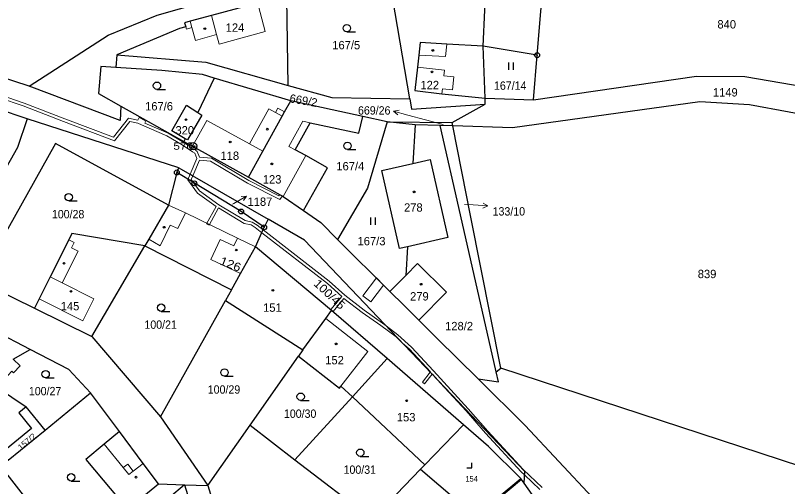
# Model space of a CAD drawing. Extents: x -758887 to -754328, y -1031688 to -1029144.
# Drawn here: x -756179.9 to -756022.6, y -1030514 to -1030418.1 of the extents above; entities that cross this region are included whole.
import ezdxf
from ezdxf.enums import TextEntityAlignment as Align

# ---------------------------------------------------------------- set-up
doc = ezdxf.new("R2010")
doc.units = 0
doc.header["$LTSCALE"] = 0.68
for name, color, linetype, lineweight in [('1', 7, 'Continuous', 25), ('13', 7, 'Continuous', 13), ('3', 7, 'Continuous', 25), ('4', 7, 'Continuous', 13), ('5', 7, 'Continuous', 25), ('7', 7, 'Continuous', 13), ('8', 7, 'Continuous', 25)]:
    doc.layers.add(name, color=color, linetype=linetype, lineweight=lineweight)
doc.layers.add('2', color=7, linetype='Continuous')

msp = doc.modelspace()

# ---------------------------------------------------------------- linework, layer by layer
at = {"layer": '1'}
for p, q in [((-756073.62, -1030426.17), (-756084.58, -1030424.35)), ((-756159.24, -1030426.06), (-756159.41, -1030428.66)), ((-756177.1, -1030432.5), (-756186.27, -1030429.51)), ((-756139.4, -1030430.81), (-756142.74, -1030437.81)), ((-756123.8, -1030435.45), (-756139.4, -1030430.81)), ((-756084.18, -1030436.12), (-756084.22, -1030434.94)), ((-756177.49, -1030439.12), (-756185.37, -1030436.47)), ((-756109.09, -1030438.68), (-756123.8, -1030435.45)), ((-756090.93, -1030439.9), (-756084.18, -1030436.12)), ((-756146.57, -1030449.09), (-756177.49, -1030439.12)), ((-756104.15, -1030439.76), (-756109.09, -1030438.68)), ((-756104.15, -1030439.76), (-756090.93, -1030439.9)), ((-756098.46, -1030440.33), (-756104.15, -1030439.76)), ((-756090.8, -1030440.57), (-756090.93, -1030439.9)), ((-756098.46, -1030440.33), (-756098.95, -1030448.2)), ((-756093.4, -1030440.49), (-756098.46, -1030440.33)), ((-756090.8, -1030440.57), (-756093.4, -1030440.49)), ((-756145.3, -1030443.16), (-756145.56, -1030443.71)), ((-756147.01, -1030450.03), (-756146.57, -1030449.09)), ((-756146.57, -1030449.09), (-756128.38, -1030459.56)), ((-756128.38, -1030459.56), (-756129.21, -1030461.2)), ((-756131, -1030465.16), (-756129.21, -1030461.2)), ((-756114.26, -1030463.66), (-756103.59, -1030474.26)), ((-756091.81, -1030463.3), (-756100.01, -1030465.15)), ((-756115.47, -1030478.16), (-756131, -1030465.16)), ((-756103.59, -1030474.26), (-756100.37, -1030470.99)), ((-756135.9, -1030473.95), (-756137.1, -1030476.09)), ((-756092.08, -1030474.4), (-756097.71, -1030480.11)), ((-756137.1, -1030476.09), (-756121.35, -1030486.18)), ((-756180.37, -1030488.07), (-756176.86, -1030486.08)), ((-756081.94, -1030490.6), (-756081.04, -1030489.91)), ((-756113.89, -1030493.93), (-756113.58, -1030493.55)), ((-756113.58, -1030493.55), (-756111.25, -1030495.74)), ((-756183.66, -1030493.75), (-756177.71, -1030497.78)), ((-756173.85, -1030502.5), (-756164.57, -1030494.9)), ((-756158.71, -1030502.76), (-756164.57, -1030494.9)), ((-756122.94, -1030508.54), (-756111.25, -1030495.74)), ((-756150.36, -1030499.82), (-756140.69, -1030513.8)), ((-756132.1, -1030501.51), (-756122.94, -1030508.54)), ((-756076.82, -1030512.55), (-756076.96, -1030512.35)), ((-756145.46, -1030513.63), (-756148.51, -1030516.24)), ((-756140.69, -1030513.8), (-756139.63, -1030517.33)), ((-756076.28, -1030513.28), (-756076.82, -1030512.55)), ((-756074.6, -1030515.58), (-756076.28, -1030513.28))]:
    msp.add_line(p, q, dxfattribs=at)
for points in [[(-756177.1, -1030432.5), (-756161.02, -1030422.06), (-756151.02, -1030418.01), (-756091.41, -1030401.05), (-756048.53, -1030383.75), (-756038.26, -1030382.8), (-756029.12, -1030383.41)], [(-756084.22, -1030434.94), (-756074.39, -1030435.22), (-756073.62, -1030426.17), (-756072.87, -1030417.3), (-756071.16, -1030397.2), (-756083.61, -1030402.28)], [(-756084.58, -1030424.35), (-756083.61, -1030402.28), (-756104.05, -1030408.71)], [(-756099.56, -1030435.05), (-756104.05, -1030408.71), (-756124.62, -1030414.55)], [(-756159.24, -1030426.06), (-756141.08, -1030427.61), (-756124.32, -1030432.31), (-756124.62, -1030414.55)], [(-756124.62, -1030414.55), (-756130.39, -1030416.19), (-756130.55, -1030415.6), (-756139.97, -1030418.11), (-756144.28, -1030419.26), (-756145.41, -1030419.56), (-756145.19, -1030420.4), (-756146.46, -1030420.76), (-756159.24, -1030426.06)], [(-756002.56, -1030425.47), (-756003.83, -1030436.47), (-756008.02, -1030441.53), (-756014.19, -1030439.23), (-756030.36, -1030436.26), (-756040.48, -1030435.67), (-756078.66, -1030440.94), (-756090.8, -1030440.57)], [(-756074.39, -1030435.22), (-756041.14, -1030430.43), (-756031.32, -1030430.49), (-756011.88, -1030433.81), (-756002.56, -1030425.47)], [(-756159.41, -1030428.66), (-756162.47, -1030428.46), (-756162.99, -1030433.99), (-756158.39, -1030436.56), (-756145.56, -1030443.71)], [(-756139.4, -1030430.81), (-756141.8, -1030430.09), (-756150.09, -1030429.28), (-756159.41, -1030428.66)], [(-756158.39, -1030436.56), (-756158.54, -1030439.45), (-756177.1, -1030432.5)], [(-756124.32, -1030432.31), (-756115.46, -1030434.8), (-756099.56, -1030435.05)], [(-756099.56, -1030435.05), (-756099.2, -1030437.14), (-756084.18, -1030436.12)], [(-756145.3, -1030443.16), (-756148.05, -1030441.57), (-756145.03, -1030436.36), (-756142.74, -1030437.81)], [(-756132.39, -1030450.99), (-756129.46, -1030445.69), (-756125.55, -1030438.6), (-756125.06, -1030437.73), (-756123.8, -1030435.45)], [(-756142.74, -1030437.81), (-756141.88, -1030438.35), (-756144.84, -1030443.42), (-756145.3, -1030443.16)], [(-756177.49, -1030439.12), (-756179.45, -1030444.96), (-756182.43, -1030450.22), (-756185.07, -1030453.38), (-756190.89, -1030458.98), (-756194.45, -1030461.45)], [(-756121.19, -1030457.81), (-756116.32, -1030449.08), (-756120.75, -1030446.6), (-756122.91, -1030445.4), (-756119.84, -1030439.91), (-756109.91, -1030442.01), (-756109.09, -1030438.68)], [(-756104.15, -1030439.76), (-756108.19, -1030453.27), (-756114.26, -1030463.66)], [(-756081.94, -1030490.6), (-756089.25, -1030458.65), (-756093.4, -1030440.49)], [(-756081.04, -1030489.91), (-756087.13, -1030459.12), (-756090.8, -1030440.57)], [(-756148.68, -1030456.69), (-756171.73, -1030444.13), (-756185.68, -1030469.03), (-756184.6, -1030473.45), (-756176.03, -1030477.68)], [(-756145.56, -1030443.71), (-756143.81, -1030444.68), (-756132.39, -1030450.99)], [(-756100.01, -1030465.15), (-756101.66, -1030465.52), (-756105.25, -1030449.62), (-756098.95, -1030448.2), (-756095.4, -1030447.4), (-756091.81, -1030463.3)], [(-756129.21, -1030461.2), (-756133.92, -1030457.98), (-756143.43, -1030452.25), (-756147.01, -1030450.03), (-756148.68, -1030456.69)], [(-756132.39, -1030450.99), (-756125.36, -1030454.91), (-756121.19, -1030457.81)], [(-756148.68, -1030456.69), (-756152.73, -1030463.63), (-756153.5, -1030464.95), (-756135.9, -1030473.95)], [(-756121.19, -1030457.81), (-756117.7, -1030460.24), (-756114.26, -1030463.66)], [(-756076.28, -1030513.28), (-756076.15, -1030510.91), (-756120.98, -1030463.81), (-756128.38, -1030459.56)], [(-756153.5, -1030464.95), (-756168.36, -1030462.45), (-756169.01, -1030463.74), (-756172.81, -1030471.29), (-756175.06, -1030475.76), (-756176.03, -1030477.68)], [(-756176.03, -1030477.68), (-756164.32, -1030483.47), (-756153.5, -1030464.95)], [(-756135.9, -1030473.95), (-756134.05, -1030470.63), (-756131, -1030465.16)], [(-756100.01, -1030465.15), (-756100.37, -1030470.99), (-756097.98, -1030468.57), (-756092.08, -1030474.4)], [(-756097.71, -1030480.11), (-756100.75, -1030477.09), (-756103.59, -1030474.26)], [(-756164.32, -1030483.47), (-756150.36, -1030499.82), (-756137.1, -1030476.09)], [(-756176.86, -1030486.08), (-756191.51, -1030478.5), (-756196.35, -1030487.29)], [(-756121.35, -1030486.18), (-756116.65, -1030479.75), (-756115.47, -1030478.16)], [(-756111.25, -1030495.74), (-756104.15, -1030487.95), (-756115.47, -1030478.16)], [(-756097.71, -1030480.11), (-756093.96, -1030483.83), (-756085.66, -1030492.03)], [(-756164.57, -1030494.9), (-756169.02, -1030490.14), (-756176.86, -1030486.08)], [(-756121.35, -1030486.18), (-756122.25, -1030487.42), (-756113.89, -1030493.93)], [(-756183.66, -1030493.75), (-756180.63, -1030490.5), (-756180.26, -1030490.84), (-756178.95, -1030489.42), (-756180.37, -1030488.07)], [(-756140.69, -1030513.8), (-756132.1, -1030501.51), (-756122.25, -1030487.42)], [(-756111.25, -1030495.74), (-756096.52, -1030509.6), (-756088.61, -1030501.4), (-756104.15, -1030487.95)], [(-756000.74, -1030512.89), (-756019.93, -1030509.92), (-756081.04, -1030489.91)], [(-756085.66, -1030492.03), (-756081.46, -1030492.68), (-756081.94, -1030490.6)], [(-756056.08, -1030523.3), (-756062.34, -1030516.25), (-756076.02, -1030501.54), (-756085.66, -1030492.03)], [(-756177.71, -1030497.78), (-756179.18, -1030498.98), (-756176.58, -1030502.15), (-756182.62, -1030507.1), (-756181.35, -1030508.64)], [(-756181.35, -1030508.64), (-756173.85, -1030502.5), (-756177.71, -1030497.78)], [(-756076.96, -1030512.35), (-756083.49, -1030505.82), (-756088.61, -1030501.4)], [(-756158.71, -1030502.76), (-756161.82, -1030505.36), (-756165.54, -1030508.47), (-756157.04, -1030518.62), (-756150.75, -1030513.43)], [(-756150.75, -1030513.43), (-756153.83, -1030509.3), (-756158.71, -1030502.76)], [(-756181.35, -1030508.64), (-756182.88, -1030509.9), (-756168.68, -1030528.11)], [(-756122.94, -1030508.54), (-756107.17, -1030520.63), (-756097.36, -1030510.47)], [(-756096.52, -1030509.6), (-756097.36, -1030510.47), (-756086.2, -1030520.01), (-756076.96, -1030512.35)], [(-756150.75, -1030513.43), (-756145.46, -1030513.63), (-756140.69, -1030513.8)], [(-756145.46, -1030513.63), (-756140.48, -1030529.53), (-756141.51, -1030530.23)], [(-756076.82, -1030512.55), (-756081.44, -1030516.41), (-756079.31, -1030519.4), (-756074.6, -1030515.58)]]:
    msp.add_lwpolyline(points, dxfattribs=at)
msp.add_lwpolyline([(-756084.58, -1030424.35), (-756092, -1030423.92), (-756097.44, -1030423.61), (-756097.69, -1030426.13), (-756097.97, -1030428.61), (-756098.51, -1030433.38), (-756093.03, -1030434), (-756084.22, -1030434.94)], close=True, dxfattribs=at)
at = {"layer": '13'}
for points in [[(-756183.19, -1030434.83), (-756178.28, -1030436.47), (-756170.07, -1030439.67), (-756159.7, -1030443.6)], [(-756159.7, -1030443.6), (-756156.59, -1030439.67), (-756154.96, -1030440.01), (-756154.2, -1030440.34), (-756149.07, -1030442.61), (-756145.9, -1030444.43), (-756143.81, -1030445.84), (-756143.37, -1030446.14), (-756142.91, -1030447.21), (-756144.29, -1030450.4), (-756143.77, -1030450.7), (-756142.39, -1030447.53), (-756140.15, -1030447.73), (-756132.62, -1030452.21), (-756126.04, -1030455.55), (-756125.5, -1030454.83), (-756126.03, -1030454.53), (-756126.22, -1030454.79), (-756132.34, -1030451.69), (-756139.97, -1030447.15), (-756142.38, -1030446.93), (-756142.89, -1030445.74), (-756143.23, -1030445.51), (-756143, -1030445.13), (-756143.52, -1030444.84), (-756143.73, -1030445.17), (-756145.58, -1030443.93), (-756148.79, -1030442.07), (-756153.52, -1030439.98), (-756153.36, -1030439.73), (-756153.51, -1030439.45), (-756154.69, -1030438.87), (-756154.95, -1030439.4), (-756156.83, -1030439.01), (-756159.9, -1030442.88), (-756169.85, -1030439.11), (-756178.08, -1030435.91), (-756183.01, -1030434.25)], [(-756072.61, -1030514.16), (-756076.46, -1030510.55), (-756083.66, -1030502.71), (-756087.64, -1030498.17), (-756094.74, -1030490.44), (-756099.21, -1030485.63), (-756101.97, -1030483.08), (-756104.35, -1030481.29), (-756105.11, -1030480.71), (-756108.87, -1030478.1), (-756112.81, -1030475.03), (-756115.96, -1030472.18), (-756129.45, -1030461.74), (-756129.71, -1030462.3), (-756116.34, -1030472.64), (-756113.42, -1030475.28), (-756115.65, -1030477.97), (-756115.18, -1030478.34), (-756112.97, -1030475.67), (-756109.23, -1030478.58), (-756105.47, -1030481.19), (-756102.35, -1030483.54), (-756101.1, -1030484.7), (-756099.63, -1030486.05), (-756095.36, -1030490.66), (-756095.39, -1030490.7), (-756096.99, -1030492.72), (-756096.53, -1030493.11), (-756094.97, -1030491.14), (-756094.94, -1030491.1), (-756093.28, -1030492.91), (-756088.08, -1030498.57), (-756084.1, -1030503.11), (-756076.88, -1030510.97), (-756076.19, -1030511.62), (-756073.05, -1030514.58)]]:
    msp.add_lwpolyline(points, dxfattribs=at)
for points in [[(-756142.84, -1030444.88), (-756143.37, -1030444.6), (-756143.52, -1030444.84), (-756143, -1030445.13)], [(-756133.28, -1030460.4), (-756131.88, -1030460.69), (-756131.03, -1030461.28), (-756129.71, -1030462.3), (-756129.45, -1030461.74), (-756130.67, -1030460.8), (-756131.64, -1030460.13), (-756133.06, -1030459.84), (-756138.46, -1030456.61), (-756142.39, -1030453.81), (-756144.09, -1030451.44), (-756143.77, -1030450.7), (-756144.29, -1030450.4), (-756144.77, -1030451.52), (-756142.81, -1030454.25), (-756139.02, -1030456.94), (-756140.95, -1030460.53), (-756140.41, -1030460.79), (-756138.51, -1030457.27)], [(-756104.9, -1030472.96), (-756106.36, -1030471.52), (-756109.1, -1030475.19), (-756107.48, -1030476.41)]]:
    msp.add_lwpolyline(points, close=True, dxfattribs=at)
at = {"layer": '3'}
for p, q in [((-756112.393, -1030421.41), (-756110.643, -1030421.41)), ((-756079.401, -1030429.13), (-756079.401, -1030427.63)), ((-756078.4, -1030429.13), (-756078.4, -1030427.63)), ((-756151.053, -1030433.13), (-756149.303, -1030433.13)), ((-756112.263, -1030445.36), (-756110.513, -1030445.36)), ((-756169.033, -1030455.83), (-756167.283, -1030455.83)), ((-756107.511, -1030460.68), (-756107.511, -1030459.18)), ((-756106.51, -1030460.68), (-756106.51, -1030459.18)), ((-756150.193, -1030478.32), (-756148.443, -1030478.32)), ((-756173.733, -1030491.86), (-756171.983, -1030491.86)), ((-756137.293, -1030491.53), (-756135.543, -1030491.53)), ((-756121.783, -1030496.45), (-756120.033, -1030496.45)), ((-756109.633, -1030507.85), (-756107.883, -1030507.85)), ((-756168.533, -1030512.86), (-756166.783, -1030512.86))]:
    msp.add_line(p, q, dxfattribs=at)
msp.add_lwpolyline([(-756087.941, -1030510.18), (-756086.94, -1030510.18), (-756086.94, -1030509.18)], dxfattribs=at)
for centre in [(-756112.3929, -1030420.6598), (-756151.0529, -1030432.3798), (-756112.2629, -1030444.6098), (-756169.0329, -1030455.0798), (-756150.1929, -1030477.5698), (-756173.7329, -1030491.1098), (-756137.2929, -1030490.7798), (-756121.7829, -1030495.6998), (-756109.6329, -1030507.0998), (-756168.5329, -1030512.1098)]:
    msp.add_circle(centre, 0.75, dxfattribs=at)
at = {"layer": '4'}
for p, q in [((-756130.39, -1030416.19), (-756129.02, -1030421.33)), ((-756138.93, -1030421.98), (-756139.97, -1030418.11)), ((-756143.96, -1030420.53), (-756144.28, -1030419.26)), ((-756145.19, -1030420.4), (-756145.07, -1030420.84)), ((-756145.07, -1030420.84), (-756143.96, -1030420.53)), ((-756143.96, -1030420.53), (-756143.22, -1030423.18)), ((-756138.93, -1030421.98), (-756143.22, -1030423.18)), ((-756138.93, -1030421.98), (-756138.36, -1030423.91)), ((-756138.36, -1030423.91), (-756129.02, -1030421.33)), ((-756092, -1030423.92), (-756092.25, -1030426.44)), ((-756097.69, -1030426.13), (-756092.25, -1030426.44)), ((-756092.49, -1030429.22), (-756097.97, -1030428.61)), ((-756132.2, -1030444.24), (-756128.26, -1030437.1)), ((-756126.9, -1030437.85), (-756125.55, -1030438.6)), ((-756140.91, -1030439.43), (-756143.81, -1030444.68)), ((-756120.75, -1030446.6), (-756125.36, -1030454.91)), ((-756146.8, -1030461.48), (-756145.25, -1030458.28)), ((-756150.38, -1030464.97), (-756148.33, -1030460.74)), ((-756148.33, -1030460.74), (-756146.8, -1030461.48)), ((-756169.01, -1030463.74), (-756167.9, -1030464.31)), ((-756152.73, -1030463.63), (-756150.38, -1030464.97)), ((-756140.1, -1030467.73), (-756138.16, -1030463.67)), ((-756131, -1030465.16), (-756134.65, -1030463.41)), ((-756167.9, -1030464.31), (-756168.44, -1030465.38)), ((-756167.1, -1030466.05), (-756170.36, -1030472.53)), ((-756168.44, -1030465.38), (-756167.1, -1030466.05)), ((-756134.05, -1030470.63), (-756140.1, -1030467.73)), ((-756170.36, -1030472.53), (-756172.81, -1030471.29)), ((-756170.36, -1030472.53), (-756163.89, -1030475.79)), ((-756175.06, -1030475.76), (-756166.14, -1030480.25)), ((-756163.89, -1030475.79), (-756166.14, -1030480.25)), ((-756155.91, -1030510.86), (-756153.83, -1030509.3)), ((-756157.93, -1030510.12), (-756156.99, -1030509.41)), ((-756156.99, -1030509.41), (-756155.91, -1030510.86)), ((-756156.79, -1030511.51), (-756155.91, -1030510.86))]:
    msp.add_line(p, q, dxfattribs=at)
for points in [[(-756092.49, -1030429.22), (-756092.62, -1030430.37), (-756090.58, -1030430.6), (-756090.88, -1030433.24)], [(-756090.88, -1030433.24), (-756092.92, -1030433.01), (-756093.03, -1030434)], [(-756128.26, -1030437.1), (-756126.9, -1030437.85), (-756126.42, -1030436.98), (-756125.06, -1030437.73)], [(-756140.91, -1030439.43), (-756132.2, -1030444.24), (-756129.46, -1030445.69)], [(-756119.84, -1030439.91), (-756121.33, -1030439.6), (-756124.19, -1030444.76), (-756122.91, -1030445.4)], [(-756148.68, -1030456.69), (-756145.25, -1030458.28), (-756134.65, -1030463.41)], [(-756138.16, -1030463.67), (-756135.41, -1030464.99), (-756134.65, -1030463.41)], [(-756113.58, -1030493.55), (-756108.1, -1030486.48), (-756116.65, -1030479.75)], [(-756156.79, -1030511.51), (-756157.93, -1030510.12), (-756161.82, -1030505.36)]]:
    msp.add_lwpolyline(points, dxfattribs=at)
at = {"layer": '5'}
for centre in [(-756141.3068, -1030420.7692), (-756094.8568, -1030425.1992), (-756095.0268, -1030429.5592), (-756145.1268, -1030439.2792), (-756128.5768, -1030441.2292), (-756136.1268, -1030443.8292), (-756127.6368, -1030448.2992), (-756098.6668, -1030453.9992), (-756149.5868, -1030461.1992), (-756134.8968, -1030465.8392), (-756169.9768, -1030468.5392), (-756097.2568, -1030472.7992), (-756168.5668, -1030474.2492), (-756127.4368, -1030474.0392), (-756114.5468, -1030484.9392), (-756100.1868, -1030496.5192), (-756155.3168, -1030512.0792)]:
    msp.add_circle(centre, 0.175, dxfattribs=at)
at = {"layer": '7'}
for p, q in [((-756102.839, -1030437.593), (-756102.001, -1030438.336)), ((-756132.811, -1030454.84), (-756133.929, -1030454.907)), ((-756083.676, -1030456.859), (-756084.64, -1030456.29))]:
    msp.add_line(p, q, dxfattribs=at)
for points in [[(-756092.76, -1030440.25), (-756099.94, -1030438.37), (-756102.839, -1030437.593), (-756101.742, -1030437.369)], [(-756135.7, -1030456.5), (-756135.41, -1030456.34), (-756132.811, -1030454.84), (-756133.428, -1030455.774)], [(-756088.44, -1030456.54), (-756086.67, -1030456.65), (-756083.676, -1030456.859), (-756084.71, -1030457.289)]]:
    msp.add_lwpolyline(points, dxfattribs=at)
at = {"layer": '8'}
for centre, radius in [((-756073.62, -1030426.1699), 0.5), ((-756073.62, -1030426.1699), 0.0303), ((-756143.7, -1030444.6698), 0.75), ((-756143.7, -1030444.6698), 0.03), ((-756147.01, -1030450.0299), 0.5), ((-756147.01, -1030450.0299), 0.0303), ((-756143.43, -1030452.2499), 0.5), ((-756143.43, -1030452.2499), 0.0303), ((-756133.92, -1030457.9799), 0.5), ((-756133.92, -1030457.9799), 0.0303), ((-756129.21, -1030461.1999), 0.5), ((-756129.21, -1030461.1999), 0.0303)]:
    msp.add_circle(centre, radius, dxfattribs=at)

# ---------------------------------------------------------------- texts
at = {"layer": '2'}
for s, height, p in [('124', 1.7, (-756135.159, -1030421.39)), ('840', 1.7, (-756034.999, -1030420.726)), ('167/5', 1.7, (-756112.5, -1030424.96)), ('122', 1.7, (-756095.489, -1030433.09)), ('1149', 1.7, (-756035.29, -1030434.576)), ('167/6', 1.7, (-756150.63, -1030437.41)), ('320', 1.7, (-756145.389, -1030442.3)), ('118', 1.7, (-756136.219, -1030447.48)), ('167/4', 1.7, (-756111.67, -1030449.61)), ('123', 1.7, (-756127.599, -1030452.29)), ('1187', 1.7, (-756130.08, -1030456.84)), ('278', 1.7, (-756098.829, -1030458.02)), ('167/3', 1.7, (-756107.35, -1030464.87)), ('839', 1.7, (-756038.999, -1030471.556)), ('279', 1.7, (-756097.599, -1030476.11)), ('145', 1.7, (-756168.759, -1030478.11)), ('151', 1.7, (-756127.539, -1030478.41)), ('128/2', 1.7, (-756089.52, -1030482.17)), ('152', 1.7, (-756114.879, -1030489.11)), ('153', 1.7, (-756100.299, -1030500.72)), ('154', 1.14, (-756086.96, -1030512.98))]:
    msp.add_text(s, height=height, dxfattribs=at).set_placement(p, align=Align.CENTER)
at = {"layer": '2', "width": 0.95}
for s, p in [('167/14', (-756079.099, -1030433.21)), ('669/26', (-756106.799, -1030438.26)), ('133/10', (-756079.379, -1030458.81)), ('100/28', (-756169.149, -1030459.38)), ('100/21', (-756150.299, -1030481.87)), ('100/27', (-756173.839, -1030495.41)), ('100/29', (-756137.399, -1030495.08)), ('100/30', (-756121.889, -1030500)), ('100/31', (-756109.739, -1030511.4))]:
    msp.add_text(s, height=1.7, dxfattribs=at).set_placement(p, align=Align.CENTER)
at = {"layer": '2'}
msp.add_text('669/2', height=1.7, rotation=350, dxfattribs=at).set_placement((-756121.3481, -1030436.224), align=Align.CENTER)
for s, height, rotation, width, p in [('126', 1.7, 339, 1.15, (-756136.3716, -1030469.4905)), ('100/45', 1.7, 317, 1.1, (-756116.4732, -1030475.4716)), ('157/2', 1.14, 40, 1.1, (-756177.1989, -1030505.2614))]:
    msp.add_text(s, height=height, rotation=rotation, dxfattribs=dict(at, width=width)).set_placement(p, align=Align.CENTER)
at = {"layer": '8', "width": 1.2}
msp.add_text('570', height=1.5, dxfattribs=at).set_placement((-756143.7, -1030445.42), align=Align.RIGHT)

doc.saveas('drawing.dxf')
